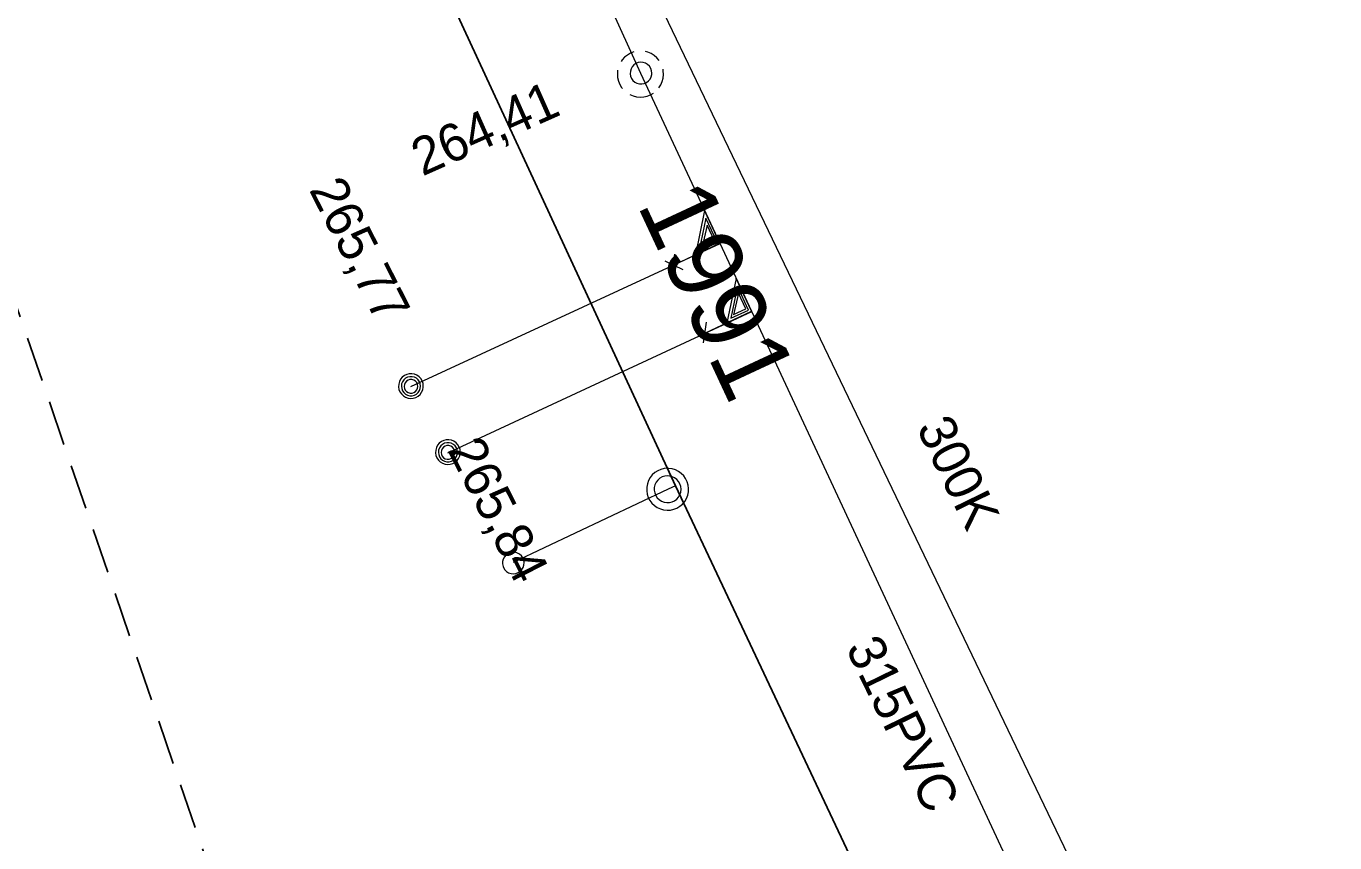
# Model space of a CAD drawing. Extents: x -732074 to -731966, y -1048695 to -1047982.
# Drawn here: x -732047.95 to -732020.02, y -1048499.57 to -1048482.15 of the extents above; entities that cross this region are included whole.
import ezdxf

# ---------------------------------------------------------------- set-up
doc = ezdxf.new("R2010")
doc.units = 0
doc.header["$LTSCALE"] = 0.32
doc.linetypes.add('MEDIUM_DASHED', pattern=[4.5, 3, -1.5])
doc.layers.add('1', color=7, linetype='Continuous')
for name, color, linetype, lineweight in [('18', 7, 'Continuous', 13), ('20', 7, 'Continuous', 13), ('49', 7, 'Continuous', 13), ('63', 7, 'MEDIUM_DASHED', 25), ('8', 7, 'Continuous', 13)]:
    doc.layers.add(name, color=color, linetype=linetype, lineweight=lineweight)

msp = doc.modelspace()

# ---------------------------------------------------------------- linework, layer by layer
at = {"layer": '18'}
for p, q in [((-732034.168, -1048487.454), (-732034.103, -1048487.015)), ((-732034.323, -1048487.152), (-732033.938, -1048487.342)), ((-732033.648, -1048488.603), (-732033.262, -1048488.794)), ((-732033.493, -1048488.905), (-732033.428, -1048488.466))]:
    msp.add_line(p, q, dxfattribs=at)
for points in [[(-732034.982, -1048482.697), (-732035.053, -1048482.725), (-732035.12, -1048482.764), (-732035.18, -1048482.812), (-732035.231, -1048482.869), (-732035.255, -1048482.903)], [(-732034.441, -1048482.88), (-732034.491, -1048482.822), (-732034.549, -1048482.772), (-732034.614, -1048482.731), (-732034.685, -1048482.702), (-732034.734, -1048482.688)], [(-732035.327, -1048483.089), (-732035.333, -1048483.166), (-732035.328, -1048483.243), (-732035.311, -1048483.318), (-732035.282, -1048483.389), (-732035.242, -1048483.455), (-732035.226, -1048483.477)], [(-732034.446, -1048483.466), (-732034.405, -1048483.401), (-732034.374, -1048483.331), (-732034.355, -1048483.256), (-732034.347, -1048483.18), (-732034.352, -1048483.103), (-732034.358, -1048483.068)], [(-732035.069, -1048483.606), (-732034.999, -1048483.637), (-732034.924, -1048483.656), (-732034.848, -1048483.663), (-732034.771, -1048483.658), (-732034.696, -1048483.641), (-732034.624, -1048483.613), (-732034.564, -1048483.578)], [(-732034.138, -1048487.244), (-732033.144, -1048486.781), (-732033.47, -1048486.082), (-732033.668, -1048487.025)], [(-732033.583, -1048486.929), (-732033.206, -1048486.753), (-732033.444, -1048486.241), (-732033.584, -1048486.929)], [(-732033.527, -1048486.851), (-732033.263, -1048486.728), (-732033.419, -1048486.392), (-732033.526, -1048486.853)], [(-732033.463, -1048488.695), (-732032.469, -1048488.232), (-732032.795, -1048487.533), (-732032.993, -1048488.476)], [(-732032.908, -1048488.38), (-732032.531, -1048488.204), (-732032.769, -1048487.692), (-732032.909, -1048488.381)], [(-732032.852, -1048488.302), (-732032.588, -1048488.179), (-732032.744, -1048487.843), (-732032.851, -1048488.304)]]:
    msp.add_lwpolyline(points, dxfattribs=at)
for points in [[(-732034.598, -1048483.149), (-732034.604, -1048483.097), (-732034.622, -1048483.047), (-732034.65, -1048483.003), (-732034.688, -1048482.966), (-732034.733, -1048482.939), (-732034.783, -1048482.923), (-732034.835, -1048482.918), (-732034.887, -1048482.925), (-732034.936, -1048482.944), (-732034.98, -1048482.974), (-732035.015, -1048483.013), (-732035.041, -1048483.058), (-732035.056, -1048483.109), (-732035.059, -1048483.161), (-732035.051, -1048483.213), (-732035.03, -1048483.261), (-732035, -1048483.304), (-732034.96, -1048483.339), (-732034.914, -1048483.363), (-732034.863, -1048483.377), (-732034.811, -1048483.379), (-732034.759, -1048483.369), (-732034.711, -1048483.347), (-732034.669, -1048483.315), (-732034.636, -1048483.275), (-732034.612, -1048483.228), (-732034.6, -1048483.177)], [(-732039.475, -1048489.827), (-732039.48, -1048489.771), (-732039.497, -1048489.718), (-732039.526, -1048489.669), (-732039.565, -1048489.628), (-732039.61, -1048489.596), (-732039.663, -1048489.574), (-732039.718, -1048489.563), (-732039.774, -1048489.565), (-732039.828, -1048489.578), (-732039.879, -1048489.603), (-732039.924, -1048489.638), (-732039.96, -1048489.681), (-732039.985, -1048489.731), (-732040, -1048489.786), (-732040.002, -1048489.842), (-732039.994, -1048489.897), (-732039.973, -1048489.95), (-732039.941, -1048489.996), (-732039.901, -1048490.035), (-732039.853, -1048490.065), (-732039.801, -1048490.084), (-732039.745, -1048490.091), (-732039.688, -1048490.087), (-732039.634, -1048490.07), (-732039.585, -1048490.043), (-732039.544, -1048490.005), (-732039.511, -1048489.96), (-732039.487, -1048489.909), (-732039.475, -1048489.854)], [(-732039.534, -1048489.83), (-732039.539, -1048489.781), (-732039.558, -1048489.735), (-732039.585, -1048489.694), (-732039.622, -1048489.661), (-732039.666, -1048489.639), (-732039.715, -1048489.627), (-732039.764, -1048489.627), (-732039.811, -1048489.639), (-732039.855, -1048489.662), (-732039.892, -1048489.695), (-732039.921, -1048489.736), (-732039.938, -1048489.783), (-732039.943, -1048489.832), (-732039.936, -1048489.881), (-732039.919, -1048489.927), (-732039.891, -1048489.967), (-732039.853, -1048490), (-732039.809, -1048490.022), (-732039.761, -1048490.034), (-732039.712, -1048490.033), (-732039.664, -1048490.021), (-732039.62, -1048489.997), (-732039.583, -1048489.964), (-732039.556, -1048489.923), (-732039.539, -1048489.876)], [(-732039.593, -1048489.834), (-732039.598, -1048489.792), (-732039.615, -1048489.754), (-732039.644, -1048489.723), (-732039.678, -1048489.7), (-732039.718, -1048489.689), (-732039.761, -1048489.689), (-732039.801, -1048489.701), (-732039.835, -1048489.724), (-732039.862, -1048489.756), (-732039.879, -1048489.794), (-732039.884, -1048489.835), (-732039.879, -1048489.877), (-732039.86, -1048489.914), (-732039.833, -1048489.946), (-732039.796, -1048489.968), (-732039.757, -1048489.979), (-732039.715, -1048489.978), (-732039.674, -1048489.965), (-732039.641, -1048489.942), (-732039.614, -1048489.909), (-732039.598, -1048489.871)], [(-732038.685, -1048491.237), (-732038.691, -1048491.181), (-732038.708, -1048491.128), (-732038.737, -1048491.079), (-732038.775, -1048491.038), (-732038.821, -1048491.006), (-732038.873, -1048490.984), (-732038.928, -1048490.973), (-732038.984, -1048490.975), (-732039.039, -1048490.988), (-732039.09, -1048491.013), (-732039.134, -1048491.048), (-732039.17, -1048491.091), (-732039.195, -1048491.141), (-732039.21, -1048491.196), (-732039.213, -1048491.252), (-732039.204, -1048491.307), (-732039.183, -1048491.36), (-732039.152, -1048491.406), (-732039.112, -1048491.445), (-732039.064, -1048491.475), (-732039.011, -1048491.494), (-732038.955, -1048491.501), (-732038.899, -1048491.497), (-732038.845, -1048491.48), (-732038.796, -1048491.453), (-732038.754, -1048491.415), (-732038.721, -1048491.37), (-732038.698, -1048491.319), (-732038.686, -1048491.264)], [(-732038.744, -1048491.24), (-732038.75, -1048491.191), (-732038.768, -1048491.145), (-732038.796, -1048491.104), (-732038.833, -1048491.071), (-732038.877, -1048491.049), (-732038.925, -1048491.037), (-732038.974, -1048491.037), (-732039.022, -1048491.049), (-732039.066, -1048491.072), (-732039.103, -1048491.105), (-732039.131, -1048491.146), (-732039.148, -1048491.193), (-732039.154, -1048491.242), (-732039.147, -1048491.291), (-732039.129, -1048491.337), (-732039.101, -1048491.377), (-732039.064, -1048491.41), (-732039.02, -1048491.432), (-732038.971, -1048491.444), (-732038.922, -1048491.443), (-732038.874, -1048491.431), (-732038.831, -1048491.407), (-732038.794, -1048491.374), (-732038.766, -1048491.333), (-732038.75, -1048491.286)], [(-732038.803, -1048491.244), (-732038.809, -1048491.202), (-732038.826, -1048491.164), (-732038.854, -1048491.133), (-732038.889, -1048491.11), (-732038.929, -1048491.099), (-732038.971, -1048491.099), (-732039.011, -1048491.111), (-732039.046, -1048491.134), (-732039.073, -1048491.166), (-732039.09, -1048491.204), (-732039.095, -1048491.245), (-732039.089, -1048491.287), (-732039.071, -1048491.324), (-732039.043, -1048491.356), (-732039.007, -1048491.378), (-732038.967, -1048491.389), (-732038.925, -1048491.388), (-732038.885, -1048491.375), (-732038.851, -1048491.352), (-732038.824, -1048491.319), (-732038.808, -1048491.281)]]:
    msp.add_lwpolyline(points, close=True, dxfattribs=at)
at = {"layer": '20'}
msp.add_line((-732020.46, -1048510.78), (-732038, -1048474.23), dxfattribs=at)
msp.add_line((-732020.46, -1048510.78), (-732038, -1048474.23), dxfattribs=at)
for points in [[(-732034.829, -1048483.16), (-732035.513, -1048481.657), (-732046.05, -1048458.48), (-732047.25, -1048455.84)], [(-732034.829, -1048483.16), (-732035.513, -1048481.657), (-732046.05, -1048458.48), (-732047.25, -1048455.84)], [(-732022.17, -1048510.34), (-732032.465, -1048488.236), (-732033.14, -1048486.786), (-732034.829, -1048483.16)], [(-732022.17, -1048510.34), (-732032.465, -1048488.236), (-732033.14, -1048486.786), (-732034.829, -1048483.16)]]:
    msp.add_lwpolyline(points, dxfattribs=at)
at = {"layer": '49'}
for p, q in [((-732039.739, -1048489.84), (-732033.14, -1048486.786)), ((-732039.739, -1048489.84), (-732033.14, -1048486.786)), ((-732038.949, -1048491.25), (-732032.465, -1048488.236)), ((-732038.949, -1048491.25), (-732032.465, -1048488.236))]:
    msp.add_line(p, q, dxfattribs=at)
at = {"layer": '63'}
msp.add_lwpolyline([(-732022.871, -1048561.909), (-732073.995, -1048412.717), (-732073.996, -1048412.715), (-732073.996, -1048412.713), (-732069.268, -1048320.574)], dxfattribs=at)
at = {"layer": '8'}
for p, q in [((-732034.25, -1048492.03), (-732037.558, -1048493.594)), ((-732034.093, -1048491.956), (-732034.25, -1048492.03))]:
    msp.add_line(p, q, dxfattribs=at)
at = {"layer": '8', "lineweight": 25}
msp.add_lwpolyline([(-732043.199, -1048472.29), (-732042.854, -1048473.025), (-732034.093, -1048491.956), (-732023.079, -1048515.311), (-732013.932, -1048535.062), (-732012.27, -1048538.65), (-732009.129, -1048546.26)], dxfattribs=at)
at = {"layer": '8'}
for points in [[(-732034.26, -1048491.582), (-732034.333, -1048491.588), (-732034.404, -1048491.606), (-732034.471, -1048491.635), (-732034.532, -1048491.675), (-732034.587, -1048491.724), (-732034.632, -1048491.781), (-732034.667, -1048491.845), (-732034.692, -1048491.914), (-732034.705, -1048491.986), (-732034.706, -1048492.06), (-732034.695, -1048492.132), (-732034.672, -1048492.202), (-732034.639, -1048492.266), (-732034.595, -1048492.325), (-732034.542, -1048492.376), (-732034.482, -1048492.417), (-732034.415, -1048492.448), (-732034.345, -1048492.468), (-732034.272, -1048492.476), (-732034.199, -1048492.473), (-732034.128, -1048492.457), (-732034.06, -1048492.43), (-732033.997, -1048492.392), (-732033.942, -1048492.344), (-732033.895, -1048492.288), (-732033.858, -1048492.225), (-732033.831, -1048492.157), (-732033.816, -1048492.085), (-732033.813, -1048492.012), (-732033.822, -1048491.939), (-732033.843, -1048491.869), (-732033.875, -1048491.803), (-732033.917, -1048491.743), (-732033.968, -1048491.691), (-732034.028, -1048491.648), (-732034.093, -1048491.615), (-732034.163, -1048491.594), (-732034.235, -1048491.584)], [(-732034.26, -1048491.744), (-732034.318, -1048491.749), (-732034.374, -1048491.767), (-732034.425, -1048491.795), (-732034.469, -1048491.834), (-732034.505, -1048491.88), (-732034.53, -1048491.933), (-732034.544, -1048491.99), (-732034.546, -1048492.049), (-732034.536, -1048492.106), (-732034.514, -1048492.161), (-732034.482, -1048492.21), (-732034.441, -1048492.251), (-732034.392, -1048492.283), (-732034.337, -1048492.305), (-732034.28, -1048492.315), (-732034.221, -1048492.314), (-732034.164, -1048492.3), (-732034.111, -1048492.275), (-732034.065, -1048492.239), (-732034.026, -1048492.195), (-732033.998, -1048492.144), (-732033.98, -1048492.088), (-732033.974, -1048492.03), (-732033.98, -1048491.972), (-732033.997, -1048491.916), (-732034.026, -1048491.865), (-732034.065, -1048491.821), (-732034.111, -1048491.786), (-732034.164, -1048491.761), (-732034.221, -1048491.747)], [(-732037.762, -1048493.701), (-732037.734, -1048493.746), (-732037.697, -1048493.783), (-732037.653, -1048493.811), (-732037.603, -1048493.829), (-732037.55, -1048493.834), (-732037.498, -1048493.827), (-732037.449, -1048493.809), (-732037.405, -1048493.781), (-732037.369, -1048493.743), (-732037.342, -1048493.697), (-732037.327, -1048493.647), (-732037.322, -1048493.595), (-732037.331, -1048493.542), (-732037.35, -1048493.494), (-732037.379, -1048493.451), (-732037.419, -1048493.416), (-732037.464, -1048493.39), (-732037.515, -1048493.375), (-732037.567, -1048493.373), (-732037.619, -1048493.382), (-732037.667, -1048493.403), (-732037.71, -1048493.434), (-732037.744, -1048493.474), (-732037.769, -1048493.521), (-732037.781, -1048493.571), (-732037.783, -1048493.624), (-732037.772, -1048493.675)]]:
    msp.add_lwpolyline(points, close=True, dxfattribs=at)

# ---------------------------------------------------------------- texts
at = {"layer": '1'}
for s, height, rotation, p in [('264,41', 0.8, 24, (-732039.495, -1048485.357)), ('265,77', 0.8, 297, (-732041.924, -1048485.636)), ('1991', 1.6, 295, (-732034.922, -1048485.95)), ('300K', 0.8, 296, (-732028.959, -1048490.717)), ('265,84', 0.8, 297, (-732038.97, -1048491.183)), ('315PVC', 0.8, 296, (-732030.469, -1048495.415))]:
    msp.add_text(s, height=height, rotation=rotation, dxfattribs=at).set_placement(p)

doc.saveas('drawing.dxf')
